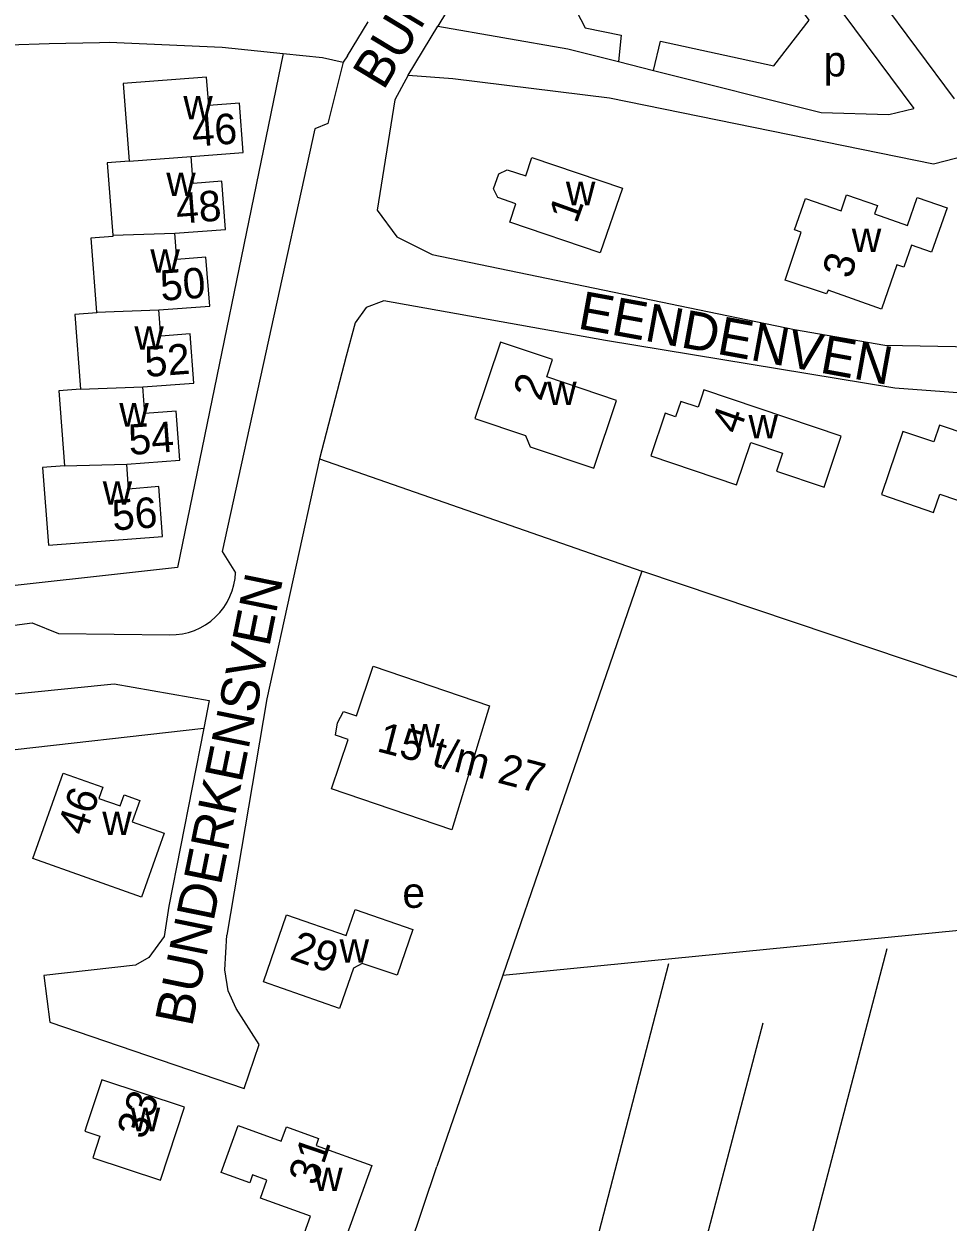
# Model space of a CAD drawing. Extents: x 162667 to 164645, y 379003 to 382150.
# Drawn here: x 163844.4 to 163965.8, y 380855.2 to 381012.5 of the extents above; entities that cross this region are included whole.
import ezdxf

# ---------------------------------------------------------------- set-up
doc = ezdxf.new("R2010")
doc.units = 0
for name, color, linetype in [('BLT_Basislijn', 7, 'Continuous'), ('BLT_Bebouwing', 7, 'Continuous'), ('BLT_Centroide', 7, 'Continuous'), ('BLT_Huisnummer', 7, 'Continuous'), ('BLT_Huisnummer_ tussenligend', 7, 'Continuous'), ('BLT_Huisnummer_reeks', 7, 'Continuous'), ('BLT_Onderverdeling_panden', 7, 'Continuous'), ('BLT_Straatnaam', 7, 'Continuous')]:
    doc.layers.add(name, color=color, linetype=linetype)

msp = doc.modelspace()

# ---------------------------------------------------------------- linework, layer by layer
at = {"layer": 'BLT_Basislijn'}
for p, q in [((163926.86, 381056.11), (163966.6, 381002.69)), ((163923.29, 381052.52), (163898.77, 381012.25)), ((163941.33, 381028.28), (163961.31, 381001.42)), ((163886.91, 381008.35), (163889.64, 381012.79)), ((163894.9, 381005.79), (163898.77, 381012.25)), ((163886.91, 381008.35), (163886.36, 381007.51)), ((163922.5, 381007.59), (163927.12, 381006.43)), ((163883.24, 380955.42), (163925.6, 380940.66)), ((163925.6, 380940.66), (163907.33, 380887.61)), ((163868.77, 380923.66), (163868.05, 380920.04)), ((163830.61, 380915.83), (163868.05, 380920.04)), ((163868.05, 380920.04), (163863.46, 380896.68)), ((163957.76, 380891.08), (163937.73, 380814.86)), ((163929.07, 380889.11), (163911.28, 380820.64)), ((163907.33, 380887.61), (163898.67, 380862.48)), ((163941.49, 380881.29), (163924.07, 380815.17)), ((163886.92, 380827.95), (163898.67, 380862.48))]:
    msp.add_line(p, q, dxfattribs=at)
for points in [[(163937.5, 381033.43), (163934.27, 381031.05), (163931.3, 381034.85), (163923.21, 381034.69), (163914.29, 381019.46), (163918.12, 381011.99), (163922.86, 381011.04), (163922.5, 381007.59)], [(163927.12, 381006.43), (163928.04, 381010.28), (163942.91, 381007.03), (163947.54, 381013.03), (163937.88, 381026.08), (163941.33, 381028.28)], [(163898.77, 381012.25), (163915.86, 381009.26), (163922.5, 381007.59)], [(163842.45, 381009.79), (163847.74, 381009.96), (163854.37, 381010.09), (163855.6, 381010.11)], [(163855.6, 381010.11), (163870.48, 381009.48), (163878.49, 381008.64)], [(163894.9, 381005.79), (163900.76, 381005.35), (163921.33, 381002.83), (163963.89, 380994.14), (163997.52, 381002.84), (164026.67, 381010.91)], [(163878.49, 381008.64), (163864.58, 380941.15), (163807.32, 380934.79)], [(163878.49, 381008.64), (163883.65, 381008.1), (163886.36, 381007.51)], [(163886.36, 381007.51), (163884.35, 380999.43), (163882.61, 380998.73), (163870.48, 380943.23), (163872.21, 380940.46)], [(163894.9, 381005.79), (163893.13, 381002.55), (163890.81, 380988.05), (163893.42, 380984.57), (163898.06, 380982.24), (163945.62, 380972.39), (163957.51, 380970.36), (163971.43, 380970.07), (163990.27, 380969.2), (164007.39, 380968.33), (164010.87, 380968.91), (164012.32, 380970.36), (164015.09, 380977.05)], [(163927.12, 381006.43), (163949.15, 381000.88), (163958.04, 381000.64), (163961.31, 381001.42)], [(164019.24, 380975.7), (164021.66, 380974.92), (164011.51, 380944.55), (164004.38, 380947.06), (164007.96, 380957.89), (164007.1, 380960.49), (164004.49, 380962.24), (163999.56, 380962.82), (163970.03, 380963.88), (163958.82, 380964.68), (163920.8, 380970.94), (163891.68, 380976.16), (163889.36, 380975.29), (163887.91, 380973.26), (163886.75, 380968.91), (163883.24, 380955.42)], [(163883.24, 380955.42), (163876.33, 380923.9), (163871.06, 380892.85)], [(164045.09, 380900.47), (163925.6, 380940.66)], [(163863.6, 380932.31), (163864.42, 380932.34), (163865.24, 380932.44), (163866.04, 380932.63), (163866.82, 380932.89), (163867.57, 380933.23), (163868.29, 380933.63), (163868.96, 380934.11), (163869.58, 380934.65), (163870.15, 380935.24), (163870.66, 380935.89), (163871.1, 380936.59), (163871.48, 380937.32), (163871.77, 380938.09), (163872, 380938.88), (163872.15, 380939.69), (163872.21, 380940.46)], [(163815.01, 380927.97), (163816.74, 380930.05), (163845.52, 380933.87), (163848.98, 380932.48), (163863.6, 380932.31)], [(163829.22, 380919.99), (163838.24, 380921.38), (163839.28, 380924.16), (163856.26, 380925.89), (163868.77, 380923.66)], [(163863.46, 380896.68), (163862.85, 380892.68), (163860.82, 380889.93), (163859.08, 380888.91), (163847.05, 380887.55), (163847.81, 380881.42), (163873.37, 380872.75), (163875.31, 380878.49), (163872.28, 380883.25), (163871.26, 380885.57), (163870.83, 380888.33), (163871.06, 380892.85)], [(163907.33, 380887.61), (163983.22, 380895.11), (163979.14, 380877.91)]]:
    msp.add_lwpolyline(points, dxfattribs=at)
at = {"layer": 'BLT_Bebouwing'}
for points in [[(163866.39, 380995.12), (163873.23, 380995.64), (163872.73, 381002.13), (163868.71, 381001.82), (163868.42, 381005.54), (163857.47, 381004.7), (163858.24, 380994.49)], [(163858.24, 380994.49), (163855.37, 380994.27), (163856.09, 380984.77)], [(163864.25, 380985.03), (163870.89, 380985.53), (163870.4, 380991.87), (163866.66, 380991.59), (163866.39, 380995.12)], [(163923.03, 380990.95), (163920.11, 380982.45), (163908.23, 380986.5), (163909.01, 380988.89), (163906.66, 380989.74), (163906.11, 380990.87), (163906.8, 380992.84), (163907.9, 380993.38), (163910.33, 380992.56), (163911.15, 380994.99), (163923.03, 380990.95)], [(163957.05, 380975.06), (163950.04, 380977.57), (163949.84, 380977.07), (163944.42, 380978.88), (163946.51, 380985.17), (163945.65, 380985.47), (163947.09, 380989.61), (163951.75, 380987.99), (163952.48, 380990.09), (163956.51, 380988.69), (163956.13, 380987.58), (163960.48, 380986.07), (163961.75, 380989.72), (163965.66, 380988.37), (163963.64, 380982.55), (163960.99, 380983.47), (163959.98, 380980.57), (163959.07, 380980.89), (163957.05, 380975.06)], [(163856.09, 380984.77), (163856.11, 380984.59), (163853.23, 380984.37), (163853.97, 380974.68)], [(163862.15, 380974.96), (163868.82, 380975.46), (163868.33, 380981.88), (163864.51, 380981.59), (163864.25, 380985.03)], [(163853.97, 380974.68), (163853.98, 380974.57), (163851.12, 380974.35), (163851.87, 380964.57)], [(163860.04, 380964.85), (163866.73, 380965.36), (163866.24, 380971.82), (163862.41, 380971.53), (163862.15, 380974.96)], [(163907.02, 380970.74), (163903.65, 380960.73), (163910.28, 380958.49), (163910.92, 380957), (163919.27, 380954.19), (163922.27, 380963.08), (163913.08, 380966.17), (163913.85, 380968.45), (163907.02, 380970.74)], [(163851.87, 380964.57), (163848.99, 380964.35), (163849.75, 380954.49)], [(163857.92, 380954.73), (163864.89, 380955.26), (163864.4, 380961.66), (163860.3, 380961.35), (163860.04, 380964.85)], [(163926.74, 380955.8), (163938.01, 380952), (163939.88, 380957.55), (163944.04, 380956.15), (163943.25, 380953.8), (163949.51, 380951.69), (163951.77, 380958.4), (163933.74, 380964.48), (163933.46, 380963.66), (163932.96, 380962.18), (163930.68, 380962.95), (163930, 380960.94), (163928.64, 380961.4), (163926.74, 380955.8)], [(163957.06, 380950.71), (163963.9, 380948.38), (163964.71, 380950.76), (163973.07, 380947.91), (163976.18, 380957.07), (163968.77, 380959.59), (163968.43, 380958.58), (163964.68, 380959.85), (163963.93, 380957.63), (163959.87, 380959.01), (163957.06, 380950.71)], [(163849.75, 380954.49), (163846.88, 380954.26), (163847.65, 380944.08), (163862.61, 380945.22), (163862.12, 380951.76), (163858.17, 380951.45), (163857.92, 380954.73)], [(163890.31, 380928.17), (163905.56, 380922.98), (163900.62, 380906.68), (163884.82, 380912.06), (163887.03, 380918.55), (163885.36, 380919.12), (163885.62, 380920.74), (163886.41, 380922.22), (163888.09, 380921.65), (163890.31, 380928.17)], [(163849.59, 380914.14), (163854.79, 380912.28), (163854.27, 380910.83), (163857.05, 380909.84), (163857.57, 380911.29), (163859.64, 380910.55), (163858.65, 380907.75), (163862.85, 380906.26), (163859.86, 380897.86), (163845.6, 380902.94), (163849.59, 380914.14)], [(163865.51, 380870.29), (163854.65, 380873.87), (163852.7, 380867.97), (163852.42, 380867.11), (163854.41, 380866.46), (163853.48, 380863.64), (163862.35, 380860.71), (163865.51, 380870.29)]]:
    msp.add_lwpolyline(points, dxfattribs=at)
for points in [[(163875.88, 380886.72), (163878.9, 380895.53), (163886.75, 380892.84), (163887.92, 380896.24), (163895.52, 380893.63), (163893.45, 380887.59), (163888.83, 380889.13), (163887.72, 380888.55), (163885.88, 380883.22)], [(163872.57, 380867.85), (163878.21, 380865.83), (163878.9, 380867.7), (163883.12, 380866.18), (163882.79, 380865.26), (163890.11, 380862.62), (163885.87, 380850.86), (163880.88, 380852.67), (163882.07, 380855.96), (163875.49, 380858.34), (163876.34, 380860.69), (163874.45, 380861.38), (163874.08, 380860.34), (163870.32, 380861.71)]]:
    msp.add_lwpolyline(points, close=True, dxfattribs=at)
at = {"layer": 'BLT_Onderverdeling_panden'}
for p, q in [((163858.24, 380994.49), (163866.39, 380995.12)), ((163856.09, 380984.77), (163864.25, 380985.03)), ((163853.97, 380974.68), (163862.15, 380974.96)), ((163851.87, 380964.57), (163860.04, 380964.85)), ((163849.75, 380954.49), (163857.92, 380954.73))]:
    msp.add_line(p, q, dxfattribs=at)

# ---------------------------------------------------------------- texts
at = {"layer": 'BLT_Centroide'}
for s, p in [('p', (163949.45, 381005.63)), ('w', (163865.36, 381000)), ('w', (163863.12, 380989.94)), ('w', (163915.61, 380988.72)), ('w', (163953.16, 380982.56)), ('w', (163861.03, 380979.84)), ('w', (163858.93, 380969.75)), ('w', (163913.15, 380962.47)), ('w', (163856.95, 380959.66)), ('w', (163939.59, 380958.09)), ('w', (163854.77, 380949.41)), ('w', (163895.19, 380917.52)), ('w', (163854.72, 380906)), ('e', (163894.13, 380896.45)), ('w', (163885.88, 380889.25)), ('w', (163858.45, 380867.12)), ('w', (163882.43, 380859.28))]:
    msp.add_text(s, height=4, dxfattribs=at).set_placement(p)
at = {"layer": 'BLT_Huisnummer'}
for s, rotation, p in [('46', 4.3631, (163866.61, 380996.39)), ('1', 70.182, (163917.01, 380986.19)), ('3', 75.3644, (163953.1, 380978.95)), ('50', 4.3631, (163862.46, 380976.15)), ('2', 70.3603, (163912.31, 380962.87)), ('4', 70.3603, (163938.34, 380958.5)), ('56', 4.3631, (163856.14, 380945.99)), ('46', 71.5822, (163852.51, 380905.76)), ('29', 340.6143, (163879.18, 380889.77)), ('33', 71.0675, (163860.29, 380865.91)), ('31', 71.2193, (163882.84, 380859.84))]:
    msp.add_text(s, height=4, rotation=rotation, dxfattribs=at).set_placement(p)
at = {"layer": 'BLT_Huisnummer_ tussenligend'}
for s, p in [('48', (163864.54, 380986.27)), ('52', (163860.43, 380966.15)), ('54', (163858.3, 380955.91))]:
    msp.add_text(s, height=4, rotation=4.3631, dxfattribs=at).set_placement(p)
at = {"layer": 'BLT_Huisnummer_reeks'}
msp.add_text('15 t/m 27', height=4, rotation=345.4413, dxfattribs=at).set_placement((163890.64, 380917.04))
at = {"layer": 'BLT_Straatnaam'}
for s, rotation, p in [('BUNDERKENSVEN', 58.8379, (163891.64, 381003.68)), ('EENDENVEN', 349.6937, (163917.02, 380972.55)), ('BUNDERKENSVEN', 78.5177, (163866.5, 380880.72))]:
    msp.add_text(s, height=5, rotation=rotation, dxfattribs=at).set_placement(p)

doc.saveas('drawing.dxf')
